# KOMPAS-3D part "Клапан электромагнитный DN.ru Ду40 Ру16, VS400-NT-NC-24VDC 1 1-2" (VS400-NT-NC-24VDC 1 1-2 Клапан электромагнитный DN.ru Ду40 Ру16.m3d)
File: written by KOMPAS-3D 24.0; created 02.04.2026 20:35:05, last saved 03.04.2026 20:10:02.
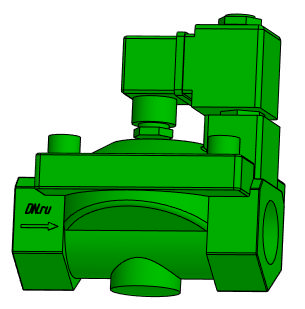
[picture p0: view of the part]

Document properties: Автор: artio; Полное имя файла: C:\Users\artio\OneDrive\Рабочий стол\Клапан электромагнитный DN.ru\VS400-NT-NC\VS400-NT-NC-24VDC 1 1-2 Клапан электромагнитный DN.ru Ду40 Ру16.m3d

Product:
- Body: Тело 1  | qty 1
    Масса: 4.144257
- Part/product: Клапан электромагнитный DN.ru Ду40 Ру16  | designation VS400-NT-NC-24VDC 1 1-2
    Масса: 2.321
    Раздел спецификации: Прочие изделия
    Примечание: D130-04730
    additional columns: ef56311e-7521-43dc-8291-0e6108b3d81d; VS400-ET-NC-220VAC 1 1-2; artio; c; Шероховатость не задана; Да

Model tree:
1. Операция без истории:1

Expressions: VS400-NT-NC-24VDC 1 1-2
